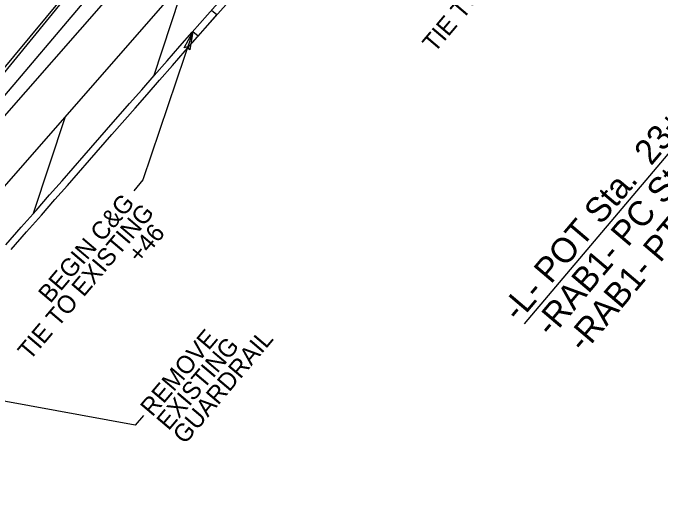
# Model space of a CAD drawing. Extents: x 1761082 to 1764358, y 421907 to 425434.
# Drawn here: x 1762006.6 to 1762189, y 422630.5 to 422771.8 of the extents above; entities that cross this region are included whole.
import ezdxf

# ---------------------------------------------------------------- set-up
doc = ezdxf.new("R2010")
doc.units = 0
for name, color, linetype in [('MARK LEFT TURN ARROW CELL', 7, 'Continuous'), ('MARK STRAIGHT RIGHT ARROW CELL', 7, 'Continuous'), ('MARK UTURN ARROW CELL', 7, 'Continuous'), ('Prop Mkg 3ft Min Skp 3ft Wide White', 7, 'Continuous'), ('Prop Mkg 3ft Min Skp 9ft Wide White', 7, 'Continuous'), ('Prop Mkg Skp Wht', 7, 'Continuous'), ('Prop Mkg Solid White Multiple Diagonals V8i', 7, 'Continuous'), ('Prop Mkg Solid Yel Skip LT', 7, 'Continuous'), ('Prop Mkg Solid Yel Skip RT', 7, 'Continuous'), ('Prop Mkg Solid Yellow Lane Line', 7, 'Continuous'), ('Scratch_Level_0', 7, 'Continuous')]:
    doc.layers.add(name, color=color, linetype=linetype)

msp = doc.modelspace()

# ---------------------------------------------------------------- linework, layer by layer
at = {"layer": 'MARK LEFT TURN ARROW CELL'}
for p, q in [((1762064.09, 422771.27), (1762062.57, 422772.56)), ((1762058.81, 422765.27), (1762057.28, 422766.56))]:
    msp.add_line(p, q, dxfattribs=at)
msp.add_lwpolyline([(1762058.81, 422765.27), (1762064.09, 422771.27)], dxfattribs=at)
at = {"layer": 'MARK STRAIGHT RIGHT ARROW CELL'}
msp.add_line((1761294.53, 421910.78), (1762672.97, 423537.92), dxfattribs=at)
at = {"layer": 'MARK UTURN ARROW CELL'}
msp.add_lwpolyline([(1762165.77, 422937.12), (1762234.28, 422783.03), (1762150.66, 422684.32)], dxfattribs=at)
at = {"layer": 'Prop Mkg 3ft Min Skp 3ft Wide White'}
msp.add_line((1761294.53, 421910.78), (1762672.97, 423537.92), dxfattribs=at)
at = {"layer": 'Prop Mkg 3ft Min Skp 9ft Wide White'}
msp.add_lwpolyline([(1762006.07, 422705.23), (1762010.45, 422710.2), (1762014.62, 422714.93), (1762018.46, 422719.3), (1762021.98, 422723.3), (1762028.23, 422730.42), (1762034.5, 422737.58), (1762041.01, 422745.03), (1762044.41, 422748.92), (1762047.93, 422752.93), (1762051.57, 422757.05), (1762055.18, 422761.15), (1762058.64, 422765.08), (1762065.09, 422772.41), (1762071.58, 422779.74), (1762074.01, 422782.47)], dxfattribs=at)
at = {"layer": 'Prop Mkg Skp Wht'}
msp.add_lwpolyline([(1762004.57, 422706.55), (1762008.95, 422711.52), (1762013.12, 422716.25), (1762016.96, 422720.62), (1762020.47, 422724.62), (1762026.72, 422731.74), (1762032.99, 422738.9), (1762039.5, 422746.35), (1762042.91, 422750.24), (1762046.43, 422754.25), (1762050.07, 422758.38), (1762053.68, 422762.47), (1762057.14, 422766.4), (1762063.59, 422773.73), (1762070.08, 422781.07), (1762072.51, 422783.8)], dxfattribs=at)
at = {"layer": 'Prop Mkg Solid White Multiple Diagonals V8i'}
msp.add_line((1761650.04, 422330.43), (1762065.62, 422830.27), dxfattribs=at)
at = {"layer": 'Prop Mkg Solid Yel Skip RT'}
for points in [[(1762057.28, 422766.56), (1762043.24, 422724.85), (1762040.64, 422721.79)], [(1762043.4, 422658.54), (1762041.06, 422655.78), (1761973.71, 422668.13)]]:
    msp.add_lwpolyline(points, dxfattribs=at)
at = {"layer": 'Prop Mkg Solid Yellow Lane Line'}
msp.add_lwpolyline([(1762054.82, 422762), (1762057.28, 422766.56), (1762056.5, 422761.41), (1762055.85, 422762.31)], close=True, dxfattribs=at)
at = {"layer": 'Scratch_Level_0'}
for p, q in [((1761856.89, 422574.6), (1762095.46, 422846.93)), ((1761842.22, 422538.12), (1762105.31, 422838.44)), ((1761856.89, 422574.6), (1762065.62, 422830.27)), ((1762055.25, 422781.3), (1762046.2, 422753.98)), ((1762021.36, 422742.62), (1762012.33, 422715.36))]:
    msp.add_line(p, q, dxfattribs=at)

# ---------------------------------------------------------------- texts
at = {"layer": 'MARK UTURN ARROW CELL'}
for s, p in [('-L- POT Sta.  23+46.92=', (1762149.13, 422684.58)), ('-RAB1- PC Sta. 10+00.00', (1762158.35, 422680.29)), ('-RAB1- PT Sta. 14+71.24', (1762167.46, 422675.9))]:
    msp.add_text(s, height=7, rotation=49.7301, dxfattribs=at).set_placement(p)
at = {"layer": 'Prop Mkg Solid Yel Skip LT'}
for s, p in [('TIE TO EXISTING', (1762125.42, 422760.43)), ('BEGIN C&G', (1762017.14, 422689.88)), ('TIE TO EXISTING', (1762011.38, 422673.8)), ('+46', (1762042.38, 422701.11)), ('REMOVE', (1762045.9, 422657.95)), ('EXISTING', (1762050.47, 422654.07)), ('GUARDRAIL', (1762055.05, 422650.2))]:
    msp.add_text(s, height=5, rotation=49.7301, dxfattribs=at).set_placement(p)

doc.saveas('drawing.dxf')
